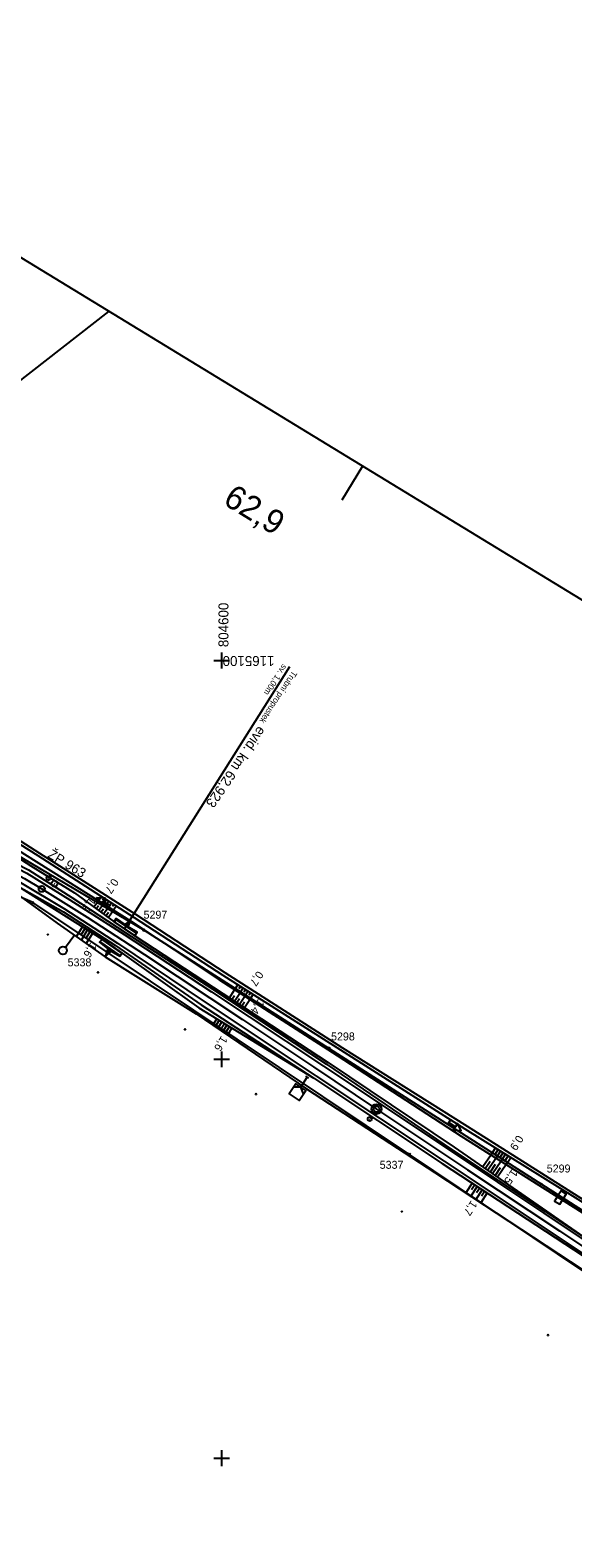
# Model space of a CAD drawing. Extents: x -804899 to -803847, y -1165742 to -1164942.
# Drawn here: x -804648 to -804511.9, y -1165320 to -1164941.9 of the extents above; entities that cross this region are included whole.
import ezdxf

# ---------------------------------------------------------------- set-up
doc = ezdxf.new("R2010")
doc.units = 0
for name, color, linetype in [('0381KM061-064P - Vrstva 1', 7, 'Continuous'), ('0381KM061-064P - Vrstva 17', 7, 'Continuous'), ('0381KM061-064P - Vrstva 19', 7, 'Continuous'), ('0381KM061-064P - Vrstva 36', 7, 'Continuous'), ('0381KM061-064P - Vrstva 4', 7, 'Continuous'), ('0381KM061-064P - Vrstva 48', 7, 'Continuous'), ('0381KM061-064P - Vrstva 49', 7, 'Continuous'), ('0381KM061-064P - Vrstva 51', 7, 'Continuous'), ('0381KM061-064P - Vrstva 55', 7, 'Continuous'), ('0381KM061-064P - Vrstva 7', 7, 'Continuous'), ('formát', 7, 'Continuous'), ('krizky_1000 - souradnice', 7, 'Continuous'), ('krizky_1000 - Vrstva 1', 7, 'Continuous'), ('szdc - hran DP', 7, 'Continuous'), ('szdc - szdc_cislo', 7, 'Continuous'), ('szdc - szdc_krizek', 7, 'Continuous'), ('vyt_sit - stávající', 7, 'Continuous')]:
    doc.layers.add(name, color=color, linetype=linetype)

msp = doc.modelspace()

# ---------------------------------------------------------------- linework, layer by layer
at = {"layer": '0381KM061-064P - Vrstva 1'}
for points in [[(-804666.44, -1165145.5), (-804649.48, -1165154.65), (-804645.14, -1165157.27), (-804633.7, -1165164.38), (-804619.36, -1165173.74)], [(-804619.36, -1165173.74), (-804594.78, -1165190.05), (-804577, -1165201.91), (-804561.16, -1165212.47), (-804538.32, -1165227.67), (-804515.3, -1165243.02), (-804489.41, -1165260.27), (-804477.81, -1165268), (-804447.6, -1165288.14), (-804422.03, -1165305.2), (-804398.19, -1165321.09), (-804394.23, -1165323.73), (-804371.85, -1165338.65), (-804349.9, -1165353.29), (-804326.64, -1165368.8), (-804303.84, -1165384.01), (-804280.33, -1165399.7), (-804257.04, -1165415.23), (-804233.85, -1165430.69)]]:
    msp.add_lwpolyline(points, dxfattribs=at)
at = {"layer": '0381KM061-064P - Vrstva 17'}
for p, q in [((-804621.51, -1165168.31), (-804626.41, -1165164.99)), ((-804625.42, -1165173.99), (-804630.34, -1165170.65))]:
    msp.add_line(p, q, dxfattribs=at)
at = {"layer": '0381KM061-064P - Vrstva 19'}
msp.add_line((-804624.36, -1165167.24), (-804582.93, -1165101.49), dxfattribs=at)
for points in [[(-804626.92, -1165165.53), (-804626.96, -1165165.56), (-804626.42, -1165164.7), (-804626.38, -1165164.82)], [(-804621.79, -1165169), (-804626.96, -1165165.56)], [(-804621.8, -1165168.94), (-804626.92, -1165165.53), (-804626.38, -1165164.82), (-804621.37, -1165168.24), (-804621.8, -1165168.94)], [(-804626.42, -1165164.7), (-804624.29, -1165166.16)], [(-804621.2, -1165168.14), (-804623.43, -1165166.8)], [(-804630, -1165169.94), (-804629.95, -1165169.87), (-804630.64, -1165170.63), (-804630.54, -1165170.53)], [(-804630.64, -1165170.63), (-804628.58, -1165172.3)], [(-804630, -1165169.94), (-804630.54, -1165170.53), (-804625.53, -1165174.1), (-804625.05, -1165173.39), (-804630, -1165169.94)], [(-804629.95, -1165169.87), (-804624.97, -1165173.36)], [(-804621.8, -1165168.94), (-804621.79, -1165169), (-804621.2, -1165168.14), (-804621.37, -1165168.24)], [(-804625.53, -1165174.17), (-804627.74, -1165172.9)], [(-804625.05, -1165173.39), (-804624.97, -1165173.36), (-804625.53, -1165174.17), (-804625.53, -1165174.1)]]:
    msp.add_lwpolyline(points, dxfattribs=at)
for centre, major_axis, ratio, start_param, end_param in [((-804623.85, -1165166.5), (0.523, -0.388), 0.037903, 2.58802, 6.935719), ((-804623.82, -1165166.48), (-0.635, 0.468), 0.043076, 0.77347, 2.26914), ((-804628.16, -1165172.59), (-0.458, 0.324), 0.038427, 2.752706, 6.687548), ((-804628.11, -1165172.52), (0.511, -0.363), 0.262854, 3.749744, 5.691062)]:
    msp.add_ellipse(centre, major_axis=major_axis, ratio=ratio, start_param=start_param, end_param=end_param, dxfattribs=at)
at = {"layer": '0381KM061-064P - Vrstva 36'}
for p, q in [((-804639.21, -1165171.9), (-804636.83, -1165168.69)), ((-804639.81, -1165172.7), (-804639.81, -1165172.7))]:
    msp.add_line(p, q, dxfattribs=at)
msp.add_circle((-804639.81, -1165172.7), 1, dxfattribs=at)
at = {"layer": '0381KM061-064P - Vrstva 4'}
for points in [[(-804760.26, -1165118.8), (-804748.36, -1165120.01), (-804721.79, -1165126), (-804699.13, -1165133.38), (-804682.38, -1165139.58), (-804672.62, -1165144.09), (-804650.43, -1165155.7), (-804639.38, -1165162.29), (-804626.13, -1165170.89), (-804604.37, -1165185.52), (-804576.36, -1165204.15)], [(-804760.26, -1165118.8), (-804748.39, -1165120.75), (-804721.77, -1165126.98), (-804699.38, -1165134.38), (-804682.72, -1165140.57), (-804673.68, -1165144.67), (-804650.96, -1165156.64), (-804639.65, -1165163.02), (-804626.64, -1165171.43)], [(-804755.73, -1165115.93), (-804748.17, -1165116.91), (-804721.25, -1165123.25), (-804698.66, -1165130.22), (-804681.33, -1165136.99), (-804671.47, -1165141.65), (-804648.84, -1165153.36), (-804638.11, -1165160.03), (-804624.48, -1165168.7), (-804602.56, -1165183.07), (-804574.47, -1165201.72), (-804542.72, -1165222.84), (-804507.36, -1165246.55), (-804477.08, -1165266.82), (-804448.75, -1165285.88), (-804421.18, -1165304.15), (-804392.89, -1165323.09), (-804369.85, -1165338.37), (-804348.86, -1165352.04), (-804325.13, -1165367.98), (-804299.32, -1165385.27), (-804266.05, -1165407.31), (-804234.28, -1165428.6)], [(-804755.73, -1165115.93), (-804748.03, -1165116.49), (-804721.05, -1165122.36), (-804698.44, -1165129.77), (-804680.98, -1165136.5), (-804671.21, -1165140.89), (-804648.42, -1165152.46), (-804637.55, -1165159.43), (-804624.04, -1165168.29), (-804602.25, -1165182.38), (-804573.74, -1165201.2), (-804542.46, -1165222.56), (-804507.06, -1165246.03), (-804476.47, -1165266.24), (-804448.31, -1165285.08), (-804421.02, -1165303.1), (-804392.59, -1165322.59), (-804369.41, -1165337.65), (-804348.68, -1165351.59), (-804324.76, -1165367.42), (-804298.9, -1165384.42), (-804265.65, -1165406.5), (-804234.05, -1165428.04)], [(-804626.64, -1165171.43), (-804605.18, -1165186.34), (-804576.91, -1165204.69), (-804544.69, -1165226.09), (-804509.35, -1165249.3), (-804478.87, -1165269.77), (-804450.06, -1165288.98), (-804422.82, -1165307.11), (-804394.42, -1165325.66), (-804371.77, -1165341.24), (-804350.46, -1165355.38), (-804326.73, -1165371.34), (-804301.47, -1165388.34), (-804268.3, -1165410.72), (-804235.74, -1165432.01)], [(-804576.36, -1165204.15), (-804544.19, -1165225.52), (-804508.95, -1165249), (-804478.52, -1165269.18), (-804449.67, -1165288.56), (-804422.62, -1165306.58), (-804394.22, -1165325.33), (-804371.37, -1165340.61), (-804350.54, -1165354.66), (-804326.31, -1165370.81), (-804300.9, -1165387.72), (-804267.8, -1165409.92), (-804235.52, -1165431.44)]]:
    msp.add_lwpolyline(points, dxfattribs=at)
at = {"layer": '0381KM061-064P - Vrstva 48'}
for p, q in [((-804632.09, -1165161.79), (-804630.93, -1165160.22)), ((-804630.19, -1165159.11), (-804630.91, -1165160.23)), ((-804629.56, -1165159.52), (-804629.91, -1165160.07)), ((-804628.93, -1165159.92), (-804629.64, -1165161.03)), ((-804628.3, -1165160.33), (-804628.65, -1165160.88)), ((-804631.49, -1165162.24), (-804630.89, -1165161.43)), ((-804630.88, -1165162.68), (-804629.66, -1165161.02)), ((-804630.28, -1165163.12), (-804629.65, -1165162.27)), ((-804629.68, -1165163.57), (-804628.39, -1165161.82)), ((-804629.07, -1165164.01), (-804628.41, -1165163.12)), ((-804628.47, -1165164.46), (-804627.11, -1165162.62)), ((-804627.66, -1165160.74), (-804628.37, -1165161.83)), ((-804627.03, -1165161.14), (-804627.38, -1165161.69)), ((-804626.4, -1165161.55), (-804627.1, -1165162.63)), ((-804636.42, -1165169.21), (-804634.88, -1165166.77)), ((-804635.19, -1165170.08), (-804633.61, -1165167.56)), ((-804635.18, -1165168.65), (-804634.24, -1165167.17)), ((-804633.93, -1165169.49), (-804632.97, -1165167.97)), ((-804633.96, -1165170.94), (-804632.34, -1165168.36)), ((-804598.06, -1165184.55), (-804596.75, -1165182.56)), ((-804595.91, -1165181.26), (-804596.74, -1165182.56)), ((-804595.28, -1165181.67), (-804595.69, -1165182.32)), ((-804594.65, -1165182.07), (-804595.48, -1165183.37)), ((-804594.01, -1165182.47), (-804594.43, -1165183.13)), ((-804593.38, -1165182.88), (-804594.21, -1165184.19)), ((-804597.43, -1165184.97), (-804596.77, -1165183.97)), ((-804596.8, -1165185.38), (-804595.48, -1165183.37)), ((-804596.18, -1165185.79), (-804595.51, -1165184.78)), ((-804595.55, -1165186.2), (-804594.22, -1165184.18)), ((-804594.92, -1165186.61), (-804594.26, -1165185.6)), ((-804594.29, -1165187.02), (-804592.96, -1165184.99)), ((-804592.75, -1165183.28), (-804593.17, -1165183.94)), ((-804592.12, -1165183.68), (-804592.95, -1165185)), ((-804602.21, -1165191.42), (-804601.25, -1165189.83)), ((-804601.2, -1165191.2), (-804600.61, -1165190.23)), ((-804600.97, -1165192.26), (-804599.97, -1165190.62)), ((-804599.94, -1165192.01), (-804599.33, -1165191.01)), ((-804599.73, -1165193.11), (-804598.69, -1165191.4)), ((-804598.68, -1165192.83), (-804598.05, -1165191.79)), ((-804598.49, -1165193.95), (-804597.41, -1165192.18)), ((-804532.42, -1165223.96), (-804534.52, -1165226.99)), ((-804532.42, -1165223.97), (-804531.32, -1165222.2)), ((-804531.34, -1165223.66), (-804530.68, -1165222.6)), ((-804531.15, -1165224.77), (-804530.05, -1165223)), ((-804530.07, -1165224.46), (-804529.41, -1165223.39)), ((-804529.88, -1165225.57), (-804528.77, -1165223.79)), ((-804528.8, -1165225.26), (-804528.14, -1165224.18)), ((-804528.61, -1165226.37), (-804527.5, -1165224.58)), ((-804532.63, -1165225.59), (-804533.9, -1165227.42)), ((-804531.15, -1165224.77), (-804533.29, -1165227.85)), ((-804531.38, -1165226.41), (-804532.67, -1165228.27)), ((-804529.88, -1165225.57), (-804532.06, -1165228.7)), ((-804530.12, -1165227.23), (-804531.44, -1165229.13)), ((-804528.61, -1165226.37), (-804530.82, -1165229.55)), ((-804537.15, -1165231.04), (-804538.77, -1165233.51)), ((-804535.89, -1165231.86), (-804537.51, -1165234.33)), ((-804536.52, -1165231.45), (-804537.33, -1165232.69)), ((-804535.27, -1165232.28), (-804536.08, -1165233.51)), ((-804534.64, -1165232.69), (-804536.26, -1165235.15)), ((-804533.39, -1165233.51), (-804535.01, -1165235.98)), ((-804534.01, -1165233.1), (-804534.82, -1165234.33))]:
    msp.add_line(p, q, dxfattribs=at)
at = {"layer": '0381KM061-064P - Vrstva 49'}
for p, q in [((-804624.29, -1165166.16), (-804622.88, -1165165.28)), ((-804623.76, -1165166.56), (-804622.88, -1165165.28)), ((-804623.43, -1165166.8), (-804622.88, -1165165.28)), ((-804643.42, -1165168.96), (-804643.77, -1165168.6)), ((-804643.42, -1165168.6), (-804643.77, -1165168.96)), ((-804628.13, -1165172.71), (-804629.21, -1165174.28)), ((-804630.84, -1165178.37), (-804631.19, -1165178.02)), ((-804630.84, -1165178.02), (-804631.19, -1165178.37)), ((-804609.02, -1165192.71), (-804609.37, -1165192.36)), ((-804609.02, -1165192.36), (-804609.37, -1165192.71)), ((-804591.22, -1165208.93), (-804591.58, -1165208.57)), ((-804591.22, -1165208.57), (-804591.58, -1165208.93)), ((-804554.65, -1165238.41), (-804555.01, -1165238.06)), ((-804554.65, -1165238.06), (-804555.01, -1165238.41)), ((-804517.98, -1165269.33), (-804518.34, -1165268.98)), ((-804517.98, -1165268.98), (-804518.34, -1165269.33))]:
    msp.add_line(p, q, dxfattribs=at)
for points in [[(-804669.51, -1165137.6), (-804647.83, -1165151.5), (-804636.87, -1165158.28), (-804626.96, -1165165.56)], [(-804668.53, -1165136.56), (-804646.51, -1165150.38), (-804635.75, -1165157.19), (-804622.88, -1165165.28), (-804600.74, -1165180), (-804571.06, -1165199.05), (-804539.91, -1165219.23), (-804504.85, -1165241.38), (-804474.07, -1165260.59), (-804445.75, -1165278.86), (-804417.38, -1165297.08), (-804386.13, -1165316.29), (-804343.68, -1165343.22), (-804323.05, -1165356.81), (-804293.41, -1165375.48), (-804263.45, -1165394.43), (-804234.68, -1165412.78)], [(-804668.09, -1165135.13), (-804646.08, -1165148.91), (-804635.34, -1165155.79), (-804621.98, -1165164.4), (-804599.68, -1165178.86), (-804570.23, -1165197.63), (-804539.04, -1165217.4), (-804503.79, -1165239.32), (-804473.21, -1165259.25), (-804445.02, -1165277.37), (-804416.3, -1165295.6), (-804385.23, -1165314.87), (-804342.84, -1165342.16), (-804322.16, -1165355.5), (-804292.15, -1165374.6), (-804262.58, -1165393.44), (-804234.25, -1165411.43)], [(-804650.96, -1165156.64), (-804629.95, -1165169.87)], [(-804651.73, -1165158.22), (-804641.24, -1165165.82), (-804629.21, -1165174.28), (-804606.38, -1165188.59), (-804578.69, -1165207.38), (-804546.55, -1165228.41), (-804509.4, -1165252.77), (-804482.02, -1165272.35), (-804454.07, -1165289.87), (-804424.02, -1165310.32)], [(-804624.29, -1165166.16), (-804626.42, -1165164.7), (-804626.96, -1165165.56)], [(-804621.79, -1165169), (-804621.2, -1165168.14), (-804623.43, -1165166.8)], [(-804629.95, -1165169.87), (-804630.64, -1165170.63), (-804628.58, -1165172.3)], [(-804621.79, -1165169), (-804602.1, -1165181.9), (-804573.29, -1165200.8), (-804541.65, -1165222.05), (-804507.06, -1165246.03), (-804476.55, -1165265.48), (-804448.31, -1165285.08)], [(-804628.58, -1165172.3), (-804629.21, -1165174.28), (-804627.74, -1165172.9)], [(-804627.74, -1165172.9), (-804625.53, -1165174.17), (-804624.97, -1165173.36)], [(-804624.97, -1165173.36), (-804605.7, -1165187.12), (-804576.91, -1165204.69)], [(-804576.91, -1165204.69), (-804544.69, -1165226.09), (-804509.35, -1165249.3), (-804478.87, -1165269.77), (-804450.06, -1165288.98), (-804422.82, -1165307.11), (-804394.42, -1165325.66), (-804371.77, -1165341.24), (-804350.46, -1165355.38), (-804326.73, -1165371.34), (-804301.47, -1165388.34), (-804268.3, -1165410.72), (-804235.74, -1165432.01)]]:
    msp.add_lwpolyline(points, dxfattribs=at)
for centre, major_axis, ratio, start_param, end_param in [((-804623.82, -1165166.48), (0.635, -0.468), 0.043076, 3.915063, 5.410733), ((-804628.11, -1165172.52), (-0.511, 0.363), 0.262854, 0.608151, 2.549469)]:
    msp.add_ellipse(centre, major_axis=major_axis, ratio=ratio, start_param=start_param, end_param=end_param, dxfattribs=at)
at = {"layer": '0381KM061-064P - Vrstva 51'}
for p, q in [((-804628.33, -1165161.87), (-804627.81, -1165161.01)), ((-804542.75, -1165215.4), (-804543.3, -1165216.24)), ((-804516.68, -1165233.05), (-804517.22, -1165233.9))]:
    msp.add_line(p, q, dxfattribs=at)
for points in [[(-804728.9, -1165105.9), (-804711.54, -1165108.67), (-804704.35, -1165111.8), (-804683.69, -1165124.09), (-804676.95, -1165128.43), (-804667.36, -1165134.41), (-804645.71, -1165148.3), (-804634.7, -1165155.23), (-804621.63, -1165163.62), (-804599.19, -1165178.23), (-804569.67, -1165197.16), (-804538.42, -1165216.77), (-804503.41, -1165238.94), (-804472.82, -1165258.55), (-804444.57, -1165276.4), (-804415.82, -1165294.73), (-804384.7, -1165314.57), (-804342.59, -1165341.72), (-804321.8, -1165355.02), (-804291.77, -1165374.22), (-804262.45, -1165392.96)], [(-804628.07, -1165161.44), (-804629.78, -1165160.4), (-804629.26, -1165159.55), (-804631.28, -1165159.49), (-804630.3, -1165161.26), (-804629.78, -1165160.4)], [(-804543.03, -1165215.82), (-804541.36, -1165216.93), (-804541.91, -1165217.76), (-804539.9, -1165217.89), (-804540.81, -1165216.09), (-804541.36, -1165216.93)], [(-804516.95, -1165233.47), (-804515.68, -1165234.27), (-804516.48, -1165235.54), (-804515.21, -1165236.34), (-804513.61, -1165233.8), (-804514.88, -1165233), (-804515.68, -1165234.27)]]:
    msp.add_lwpolyline(points, dxfattribs=at)
at = {"layer": '0381KM061-064P - Vrstva 55'}
msp.add_lwpolyline([(-804834.02, -1165173.21), (-804777.95, -1165165.95), (-804761.65, -1165133.49), (-804755.48, -1165121.19), (-804751.26, -1165114.04), (-804741.92, -1165100.8), (-804736.13, -1165096.49), (-804701.79, -1165069.72), (-804628.3, -1165012.44)], dxfattribs=at)
at = {"layer": '0381KM061-064P - Vrstva 7'}
for p, q in [((-804643.44, -1165154.52), (-804643.36, -1165154.57)), ((-804580.17, -1165206.99), (-804578.52, -1165204.48)), ((-804578.1, -1165204.76), (-804578.93, -1165204.21)), ((-804562.9, -1165214.95), (-804562.82, -1165215.01))]:
    msp.add_line(p, q, dxfattribs=at)
for points in [[(-804580.17, -1165206.99), (-804581.42, -1165206.16), (-804583.08, -1165208.66), (-804580.58, -1165210.32), (-804578.92, -1165207.81), (-804580.17, -1165206.99)], [(-804579.47, -1165208.65), (-804580.17, -1165206.99), (-804581.98, -1165206.99)]]:
    msp.add_lwpolyline(points, dxfattribs=at)
for centre, radius in [((-804645.14, -1165157.27), 0.75), ((-804643.4, -1165154.55), 0.5), ((-804561.16, -1165212.47), 1.25), ((-804561.16, -1165212.47), 0.752), ((-804562.86, -1165214.98), 0.5)]:
    msp.add_circle(centre, radius, dxfattribs=at)
at = {"layer": 'formát'}
for p, q in [((-804206.05, -1165269.84), (-804743.98, -1164941.92)), ((-804564.67, -1165051.23), (-804569.87, -1165059.77))]:
    msp.add_line(p, q, dxfattribs=at)
at = {"layer": 'krizky_1000 - Vrstva 1'}
for points in [[(-804600, -1165098), (-804600, -1165102)], [(-804602, -1165100), (-804598, -1165100)], [(-804600, -1165198), (-804600, -1165202)], [(-804602, -1165200), (-804598, -1165200)], [(-804602, -1165300), (-804598, -1165300)], [(-804600, -1165298), (-804600, -1165302)]]:
    msp.add_lwpolyline(points, dxfattribs=at)
at = {"layer": 'szdc - hran DP'}
for p, q in [((-804647.39, -1165160.7), (-804728.07, -1165125.68)), ((-804680.02, -1165131.72), (-804619.47, -1165167.61)), ((-804628.74, -1165173.15), (-804647.39, -1165160.7)), ((-804619.47, -1165167.61), (-804573.03, -1165197.25)), ((-804552.85, -1165223.84), (-804628.74, -1165173.15)), ((-804573.03, -1165197.25), (-804519.76, -1165231.32)), ((-804418.46, -1165314.18), (-804552.85, -1165223.84)), ((-804519.76, -1165231.32), (-804468.27, -1165264.32))]:
    msp.add_line(p, q, dxfattribs=at)
at = {"layer": 'szdc - szdc_krizek'}
for p, q in [((-804647.12, -1165160.97), (-804647.66, -1165160.44)), ((-804647.66, -1165160.97), (-804647.12, -1165160.44)), ((-804619.21, -1165167.88), (-804619.74, -1165167.34)), ((-804619.74, -1165167.88), (-804619.21, -1165167.34)), ((-804628.47, -1165173.42), (-804629.01, -1165172.89)), ((-804629.01, -1165173.42), (-804628.47, -1165172.89)), ((-804572.77, -1165197.52), (-804573.3, -1165196.99)), ((-804573.3, -1165197.52), (-804572.77, -1165196.99)), ((-804552.58, -1165224.1), (-804553.12, -1165223.57)), ((-804553.12, -1165224.1), (-804552.58, -1165223.57)), ((-804519.49, -1165231.58), (-804520.03, -1165231.05)), ((-804520.03, -1165231.58), (-804519.49, -1165231.05))]:
    msp.add_line(p, q, dxfattribs=at)
at = {"layer": 'vyt_sit - stávající'}
msp.add_line((-804641.97, -1165155.91), (-804641.88, -1165155.96), dxfattribs=at)
msp.add_circle((-804641.93, -1165155.93), 0.756, dxfattribs=at)

# ---------------------------------------------------------------- texts
at = {"layer": '0381KM061-064P - Vrstva 19'}
for s, height, rotation, p in [('Trubní propustek', 1.5, 236.6035, (-804582.22, -1165102.45)), ('sv. 1,00m', 1.5, 236.6035, (-804584.72, -1165100.8)), ('evid. km 62,923', 2.5, 235.6365, (-804590.77, -1165116.28))]:
    msp.add_text(s, height=height, rotation=rotation, dxfattribs=at).set_placement(p)
at = {"layer": '0381KM061-064P - Vrstva 48'}
for s, rotation, p in [('0,7', 237.184, (-804627.36, -1165154.47)), ('1,2', 233.6713, (-804633.01, -1165159.16)), ('1,6', 237.8043, (-804632.81, -1165170.52)), ('0,7', 237.4892, (-804591.05, -1165177.68)), ('1,4', 236.7324, (-804590.78, -1165184.72)), ('1,6', 238.5896, (-804600.07, -1165193.98)), ('0,9', 238.1314, (-804525.86, -1165218.85)), ('1,5', 235.2728, (-804527.19, -1165227.42)), ('1,7', 236.7061, (-804537.39, -1165235.24))]:
    msp.add_text(s, height=2, rotation=rotation, dxfattribs=at).set_placement(p)
at = {"layer": '0381KM061-064P - Vrstva 7'}
msp.add_text('62,9', height=6, rotation=328.3791, dxfattribs=at).set_placement((-804599.94, -1165060.6))
at = {"layer": 'krizky_1000 - souradnice'}
for s, rotation, p in [('804600', 90, (-804598.3, -1165096.64)), ('1165100', 180, (-804586.75, -1165098.87))]:
    msp.add_text(s, height=2.5, rotation=rotation, dxfattribs=at).set_placement(p)
at = {"layer": 'szdc - szdc_cislo'}
for s, p in [('5297', (-804619.59, -1165164.72)), ('5338', (-804638.63, -1165176.68)), ('5298', (-804572.56, -1165195.26)), ('5337', (-804560.36, -1165227.45)), ('5299', (-804518.46, -1165228.38))]:
    msp.add_text(s, height=2, dxfattribs=at).set_placement(p)
at = {"layer": 'vyt_sit - stávající'}
msp.add_text('ŽP 963', height=2.4, rotation=328.5611, dxfattribs=at).set_placement((-804643.81, -1165149.22))

doc.saveas('drawing.dxf')
